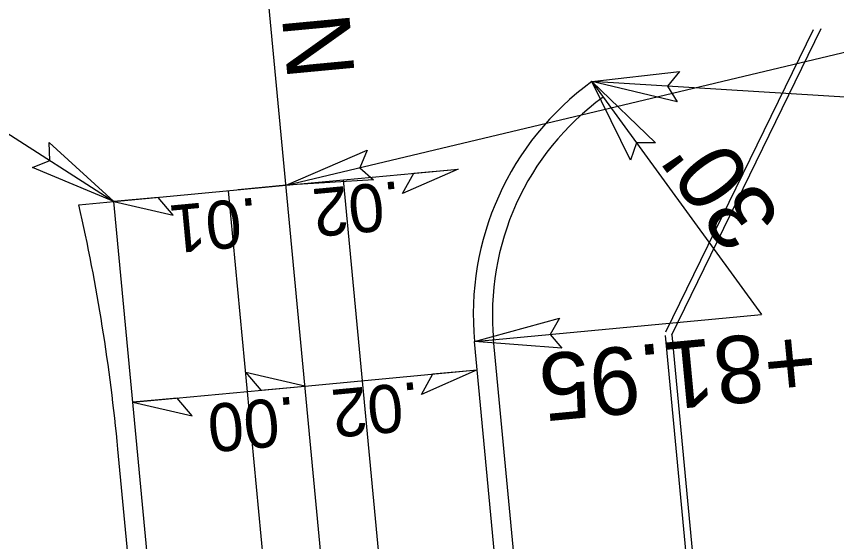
# Model space of a CAD drawing. Extents: x 1627861 to 1629601, y 761281 to 766239.
# Drawn here: x 1628256.3 to 1628341.6, y 765528.8 to 765583.5 of the extents above; entities that cross this region are included whole.
import ezdxf

# ---------------------------------------------------------------- set-up
doc = ezdxf.new("R2010")
doc.units = 0
for name, color, linetype in [('Cogo Default Point CELL', 7, 'Continuous'), ('Exist Property Tie Line Text', 7, 'Continuous'), ('Exist Right of Way Monument Text', 7, 'Continuous'), ('Exist Utilities Gas Meter CELL', 7, 'Continuous'), ('Exist Utilities Gas Meter Cogo Elevation', 7, 'Continuous'), ('Exist Utilities Gas Meter Cogo Number', 7, 'Continuous'), ('Exist Utilities Gas UG Line', 7, 'Continuous'), ('Exist Utilities Power UG Cable SUE LOS B Cogo Point CELL', 7, 'Continuous'), ('Exist Utilities Telephone UG Cable SUE LOS B Cogo Number', 7, 'Continuous'), ('Exist Utilities Water UG Line SUE LOS B Cogo Number', 7, 'Continuous'), ('Scratch_Level_0', 7, 'Continuous'), ('Typical Terminator CELL', 7, 'Continuous')]:
    doc.layers.add(name, color=color, linetype=linetype)

msp = doc.modelspace()

# ---------------------------------------------------------------- linework, layer by layer
at = {"layer": 'Exist Property Tie Line Text'}
msp.add_line((1628284.312, 765565.935), (1628279.334, 765565.465), dxfattribs=at)
at = {"layer": 'Exist Right of Way Monument Text'}
for p, q in [((1628271.09, 765514.465), (1628266.392, 765564.244)), ((1628306.931, 765517.847), (1628303.928, 765549.659))]:
    msp.add_line(p, q, dxfattribs=at)
msp.add_arc((1628333.796, 765552.478), 30, 126.07176, 185.39143, dxfattribs=at)
at = {"layer": 'Exist Utilities Gas Meter CELL'}
msp.add_line((1628289.182, 765514.331), (1628230.558, 766135.5), dxfattribs=at)
at = {"layer": 'Exist Utilities Gas Meter Cogo Elevation'}
for p, q in [((1628262.75, 765563.9), (1628266.392, 765564.244)), ((1628308.922, 765518.035), (1628305.919, 765549.847)), ((1628269.099, 765514.277), (1628266.815, 765538.472))]:
    msp.add_line(p, q, dxfattribs=at)
for centre, radius, start, end in [((1628333.796, 765552.478), 28, 126.07176, 185.39143), ((1628067.7, 765519.68), 200, 5.39143, 12.77357)]:
    msp.add_arc(centre, radius, start, end, dxfattribs=at)
at = {"layer": 'Exist Utilities Gas Meter Cogo Number'}
for points in [[(1628325.021, 765574.632), (1628316.132, 765576.726), (1628325.262, 765577.774), (1628324.017, 765576.246)], [(1628320.178, 765568.539), (1628316.132, 765576.726), (1628322.753, 765570.353), (1628320.783, 765570.341)], [(1628259.649, 765570.403), (1628266.392, 765564.244), (1628257.908, 765567.777), (1628259.739, 765568.505)], [(1628293.426, 765566.516), (1628284.312, 765565.935), (1628292.744, 765569.591), (1628291.997, 765567.768)], [(1628313.034, 765548.961), (1628303.928, 765549.659), (1628312.788, 765552.102), (1628311.793, 765550.401)]]:
    msp.add_lwpolyline(points, close=True, dxfattribs=at)
at = {"layer": 'Exist Utilities Gas UG Line'}
for p, q in [((1628294.984, 765516.72), (1628290.286, 765566.499)), ((1628283.037, 765515.592), (1628278.339, 765565.371))]:
    msp.add_line(p, q, dxfattribs=at)
at = {"layer": 'Exist Utilities Telephone UG Cable SUE LOS B Cogo Number'}
for p, q in [((1628323.853, 765550.663), (1628339.223, 765582.156)), ((1628324.452, 765550.37), (1628340.023, 765582.276)), ((1628323.788, 765550.308), (1628326.654, 765519.944)), ((1628324.452, 765550.37), (1628327.318, 765520.007))]:
    msp.add_line(p, q, dxfattribs=at)
at = {"layer": 'Exist Utilities Water UG Line SUE LOS B Cogo Number'}
for p, q in [((1628284.312, 765565.935), (1628302.233, 765567.626)), ((1628266.392, 765564.244), (1628284.312, 765565.935)), ((1628286.285, 765545.028), (1628304.206, 765546.719)), ((1628268.365, 765543.336), (1628286.285, 765545.028))]:
    msp.add_line(p, q, dxfattribs=at)
at = {"layer": 'Scratch_Level_0'}
for p, q in [((1628284.312, 765565.935), (1628649.722, 765653.114)), ((1628186.345, 765615.515), (1628266.392, 765564.244)), ((1628316.132, 765576.726), (1628333.796, 765552.478)), ((1628574.303, 765561.021), (1628316.132, 765576.726)), ((1628303.928, 765549.659), (1628333.796, 765552.478))]:
    msp.add_line(p, q, dxfattribs=at)
at = {"layer": 'Typical Terminator CELL'}
for points in [[(1628302.233, 765567.626), (1628296.447, 765565.071), (1628297.628, 765567.192)], [(1628266.392, 765564.244), (1628272.553, 765562.816), (1628270.996, 765564.678)], [(1628286.285, 765545.028), (1628280.124, 765546.455), (1628281.681, 765544.593)], [(1628304.206, 765546.719), (1628298.42, 765544.164), (1628299.601, 765546.284)], [(1628268.365, 765543.336), (1628274.526, 765541.909), (1628272.969, 765543.771)]]:
    msp.add_lwpolyline(points, close=True, dxfattribs=at)

# ---------------------------------------------------------------- texts
at = {"layer": 'Cogo Default Point CELL'}
msp.add_text('N 5%%d 23\' 29.1" W', height=7, rotation=95.39143, dxfattribs=at).set_placement((1628291.479, 765577.406))
at = {"layer": 'Exist Utilities Power UG Cable SUE LOS B Cogo Point CELL'}
for s, rotation, p in [("30'", 126.07176, (1628336.039, 765562.531)), ('+81.95', 185.39143, (1628339.178, 765551.006))]:
    msp.add_text(s, height=7, rotation=rotation, dxfattribs=at).set_placement(p)
at = {"layer": 'Exist Utilities Water UG Line SUE LOS B Cogo Number'}
for s, p in [('.02', (1628296.125, 765566.39)), ('.01', (1628281.272, 765564.674)), ('.02', (1628298.098, 765545.483)), ('.00', (1628285.214, 765543.952))]:
    msp.add_text(s, height=5, rotation=185.39143, dxfattribs=at).set_placement(p)

doc.saveas('drawing.dxf')
